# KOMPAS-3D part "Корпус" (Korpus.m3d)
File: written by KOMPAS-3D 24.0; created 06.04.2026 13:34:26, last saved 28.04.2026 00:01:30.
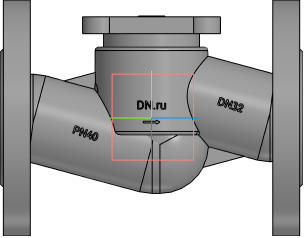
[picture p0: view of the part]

Document properties: Автор: R2D2; Полное имя файла: C:\Работа\ГОТОВЫЕ ИСХОДНИКИ\VSO2130M-F-S Клапан запорный сальниковый DN.ru Ду15-100 Ру40\исходные материалы\DN32\Korpus.m3d

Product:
- Body: Труба / Нестандартная труба / L = 114.9 мм  | qty 1  | 2 such rows
    Материал: Нестандартная труба (density 7856 kg/m3)
    Масса: 7.687658
    Раздел спецификации: Детали
    Примечание: 1,92 кг
    additional columns: Pipeline; 0.052; 0; 0; 0.002; 0.1149; true; 0.04
- Body: Тело 4  | qty 1
    Материал: Нестандартная труба (density 7856 kg/m3)
    Масса: 7.687658
- Body: Тело 5  | qty 1
    Материал: Нестандартная труба (density 7856 kg/m3)
    Масса: 7.687658
- Body: Тело 8  | qty 1
    Материал: Нестандартная труба (density 7856 kg/m3)
    Масса: 7.687658
- Body: Тело 10  | qty 1
    Материал: Нестандартная труба (density 7856 kg/m3)
    Масса: 7.687658
- Body: Тело 11  | qty 1
    Материал: Нестандартная труба (density 7856 kg/m3)
    Масса: 7.687658
- Body: Тело 12  | qty 1
    Материал: Нестандартная труба (density 7856 kg/m3)
    Масса: 7.687658
- Body: Тело 13  | qty 1
    Материал: Нестандартная труба (density 7856 kg/m3)
    Масса: 7.687658
- Part/product: Корпус
    Масса: 6.9

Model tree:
1. Труба:1  (labels: {F703FF30-5BE6-4673-A7F1-8EDA1BE1E2D1}; SHAPEOBJECT3D_ATTR_BUTT; SHAPEOBJECT3D_ATTR_VALID; SHAPEOBJECT3D_ATTR_BUTT_AREA)
     PIPE_D = 2.15639; PIPE_R = 3
2. Труба:2  (labels: {F703FF30-5BE6-4673-A7F1-8EDA1BE1E2D1}; SHAPEOBJECT3D_ATTR_BUTT; SHAPEOBJECT3D_ATTR_VALID; SHAPEOBJECT3D_ATTR_BUTT_AREA)
     PIPE_R = 3
3. Колонна
4. Элемент выдавливания:1
     Смещение 1 = -1; Смещение 2 = -5
5. Скругление:17  (with: Ребро.Элемент выдавливания:1)
     Радиус = 2
6. Скругление:18  (with: Ребро.Элемент выдавливания:1)
7. Скругление:24
     Радиус = 1.5
8. Элемент выдавливания:2
     Расстояние 1 = 6
9. Эскиз:4  (with: Грань.Элемент выдавливания:1)
10. Элемент выдавливания:3
     Расстояние 1 = 8
11. ОТЛИВКА
12. Скругление:6  (with: Грань.Элемент выдавливания:1)
     Радиус = 2
13. Элемент выдавливания:6  (with: Грань.Элемент выдавливания:1)
     Смещение 1 = 4
14. ЛЕЙБЛ
15. Элемент выдавливания:7  (with: Грань.Элемент выдавливания:1)
     Расстояние 1 = 34.4857; Смещение 1 = 1
16. Dn
17. Pn
18. Стрелочка
19. Элемент выдавливания:10  (with: Грань.Труба:1)
     Расстояние 1 = 26.9529; Смещение 1 = 1
20. Элемент выдавливания:11  (with: Грань.Труба:2)
     Расстояние 1 = 26.9917; Смещение 1 = 1
21. Элемент выдавливания:12  (with: Грань.Элемент выдавливания:1)
     Расстояние 1 = 34.4999; Смещение 1 = 1
22. Материал
23. Элемент выдавливания:13  (with: Грань.Элемент выдавливания:1)
     Расстояние 1 = 33.996; Смещение 1 = 0.5
24. Фланец верх  (with: Грань.Элемент выдавливания:3)
25. Элемент выдавливания:14
     Расстояние 1 = 10
26. Эскиз:18  (with: Грань.Элемент выдавливания:14)
27. Элемент выдавливания:15
     Расстояние 1 = 0.5
28. Эскиз:19  (with: Грань.Элемент выдавливания:14, Ребро.Элемент выдавливания:14)
29. Элемент выдавливания:16  (with: Грань.Элемент выдавливания:14)
     Расстояние 1 = 0.5; Расстояние 2 = 11; Смещение 2 = 1
30. Фланец
31. Элемент вращения:1
     Угол 1 = 360
32. отвертие во фланце  (with: Грань.Элемент вращения:1)
33. Элемент выдавливания:8
34. Массив по концентрической сетке:2  (with: Элемент выдавливания:8, Эскиз:10, Грань.Элемент вращения:1)  (4 pattern instances)
     Шаг 2 = 360
35. Зеркальный массив:1
36. Экземпляр ( 1 )
37. Экземпляр ( 2 )  (with: Элемент вращения:1, Массив по концентрической сетке:2, Экземпляр ( 1 ), Элемент выдавливания:8)
38. Экземпляр ( 3 )  (with: Элемент выдавливания:8)
39. Экземпляр ( 4 )  (with: Элемент выдавливания:8)
40. Скругление:25  (with: Ребро.Элемент выдавливания:1)
     Радиус = 2
41. Массив по концентрической сетке:3  (with: Элемент выдавливания:16, Эскиз:19)  (labels: Клапан запорный DN.ru Ду32 Ру40)  (4 pattern instances)
     Шаг 2 = 360

Expressions: DS/2+3; DN/2; LL/2; D1/2; D2/2-8
Referenced files in C:\Работа\ГОТОВЫЕ ИСХОДНИКИ\VSO2130M-F-S Клапан запорный сальниковый DN.ru Ду15-100 Ру40\исходные материалы\DN32\: VSO2130M-F-S Клапан запорный DN.ru Ду32 Ру40.a3d
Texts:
  GOST 26.020 Pr3
  var3D
  GS-C25
  смещение колонны вниз
  LL-10
  DN+20
  DS+10
  Труба / Нестандартная труба / L = %s мм
  Ось Y.Начало координат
